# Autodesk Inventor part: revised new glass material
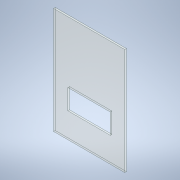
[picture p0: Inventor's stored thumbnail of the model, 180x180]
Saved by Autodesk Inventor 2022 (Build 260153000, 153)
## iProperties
Created: 2021-07
Part Number: revised new glass material
Material: Glass
Document SubType Name: Modeling
Designer: USER
Density: 2.18 g/cm^3
Appearance: Clear
Author: USER
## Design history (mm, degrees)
sketch "Sketch2"
  geometry: L1 (0, 0)-(254, 0); L2 (254, 0)-(254, -380); L3 (254, -380)-(0, -380); L4 (0, -380)-(0, 0)
  constraints: 8 end point, 2 parallel, 1 horizontal, 1 perpendicular
  dimensions: "d4" = 254 distance of L2.end L3.end; "d5" = 380 distance of L1.end L2.end
extrude "Extrusion2" new body sketch "Sketch2" distance "d6" = 6; taper "d7" = 0 deg
sketch "Sketch3"
  geometry: L1 (-202.394, -218.854)-(-51.253, -218.854); L2 (-51.253, -218.854)-(-51.253, -290.684); L3 (-51.253, -290.684)-(-202.394, -290.684); L4 (-202.394, -290.684)-(-202.394, -218.854); 1 further point
  constraints: 8 end point, 2 parallel, 1 horizontal, 1 perpendicular
extrude "Extrusion3" cut sketch "Sketch3" distance "d8" = 10; taper "d9" = 0 deg
body "Solid2"
